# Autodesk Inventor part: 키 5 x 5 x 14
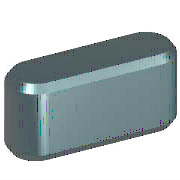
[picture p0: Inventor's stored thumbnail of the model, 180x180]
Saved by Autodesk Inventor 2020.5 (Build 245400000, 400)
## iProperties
IsCustomPart: 1
Created: 2012-02
Part Number: 키 5 x 5 x 14
Material: 강철, 연강
Description: 키 및 해당 키홈
Document SubType Name: Modeling
Standard: KS B 1311
Designer: mduedu
Standards Organization: KS
Language: ko-KR
Size Designation: 4 x 4 x 12
Categories: <MemberInstance><Categories><Category DisplayName="샤프트 부품" InternalName="7f7aeb1f-a693-4053-b835-cee3144e0d98" Mnemonic="SHFT"><Category DisplayName="키" Interna
Density: 1 g/cm^3
Appearance: 노란색
Author: mduedu
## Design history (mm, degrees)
workplane "Work Plane1"
workplane "Work Plane2"
sketch "스케치1"
  geometry: L1 (2.5, 2.5)-(11.5, 2.5); L2 (11.5, -2.5)-(2.5, -2.5); L3 (0, 8.9)-(0, -4.4) reference; L4 (-2.8, 0)-(16.8, 0) reference; L5 (14, 0)-(14, 7); A1 r 2.5 centre (2.5, 0) between (2.5, 2.5) and (2.5, -2.5); A2 r 2.5 centre (11.5, 0) between (11.5, -2.5) and (11.5, 2.5)
  constraints: 6 end point, 5 point on circle, 4 tangent, 3 point on line, 2 centre point, 1 horizontal, 1 parallel, 1 perpendicular
  dimensions: "d0" = 2.5 radius of A1 (= 0.5 x PB); "d13" = 2.5 radius of A2 (= 0.5 x PB); "d14" = 14 distance between parallel lines of L5 L3 (= NLG)
extrude "본체1" new body sketch "스케치1" taper "d3" = 0 deg; stored distance "d4" = 10
workplane "Work Plane3"
body "Solid1"
chamfer "모따기1" distance "d8" = 0.25 (= PHH); stored, may be unused: second distance "d9" = 0.25 (= PHH), angle "d15" = 45 deg
other parameters: "d1" = -3 (= -PNT), "d2" = 2 (= PH - PNT), "NLG" = 14 [user parameter; used in 3 equation terms], "PB" = 5 [user parameter; used in 2 equation terms], "PNT" = 3 [user parameter; used in 2 equation terms], "PH" = 5 [user parameter; used in 1 equation term], "PHH" = 0.25 [user parameter; used in 2 equation terms], "d10" = 0, "d16" = 0, "d17" = 0, "d18" = 0, "PLB2" = 14 (= NLG) [user parameter], "WDMAX" = 12 [user parameter], "PLB1" = 14 (= NLG) [user parameter], "RR" = 0.08 [user parameter], "PUEB" = 1.8 [user parameter]
